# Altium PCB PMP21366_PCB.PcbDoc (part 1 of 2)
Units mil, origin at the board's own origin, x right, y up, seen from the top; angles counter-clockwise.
Board outline 5900 x 4700 mil, 2 copper layers (Top Layer, Bottom Layer), stack 62 mil thick; 89 components, 44 nets, 220 pads, 54 vias.
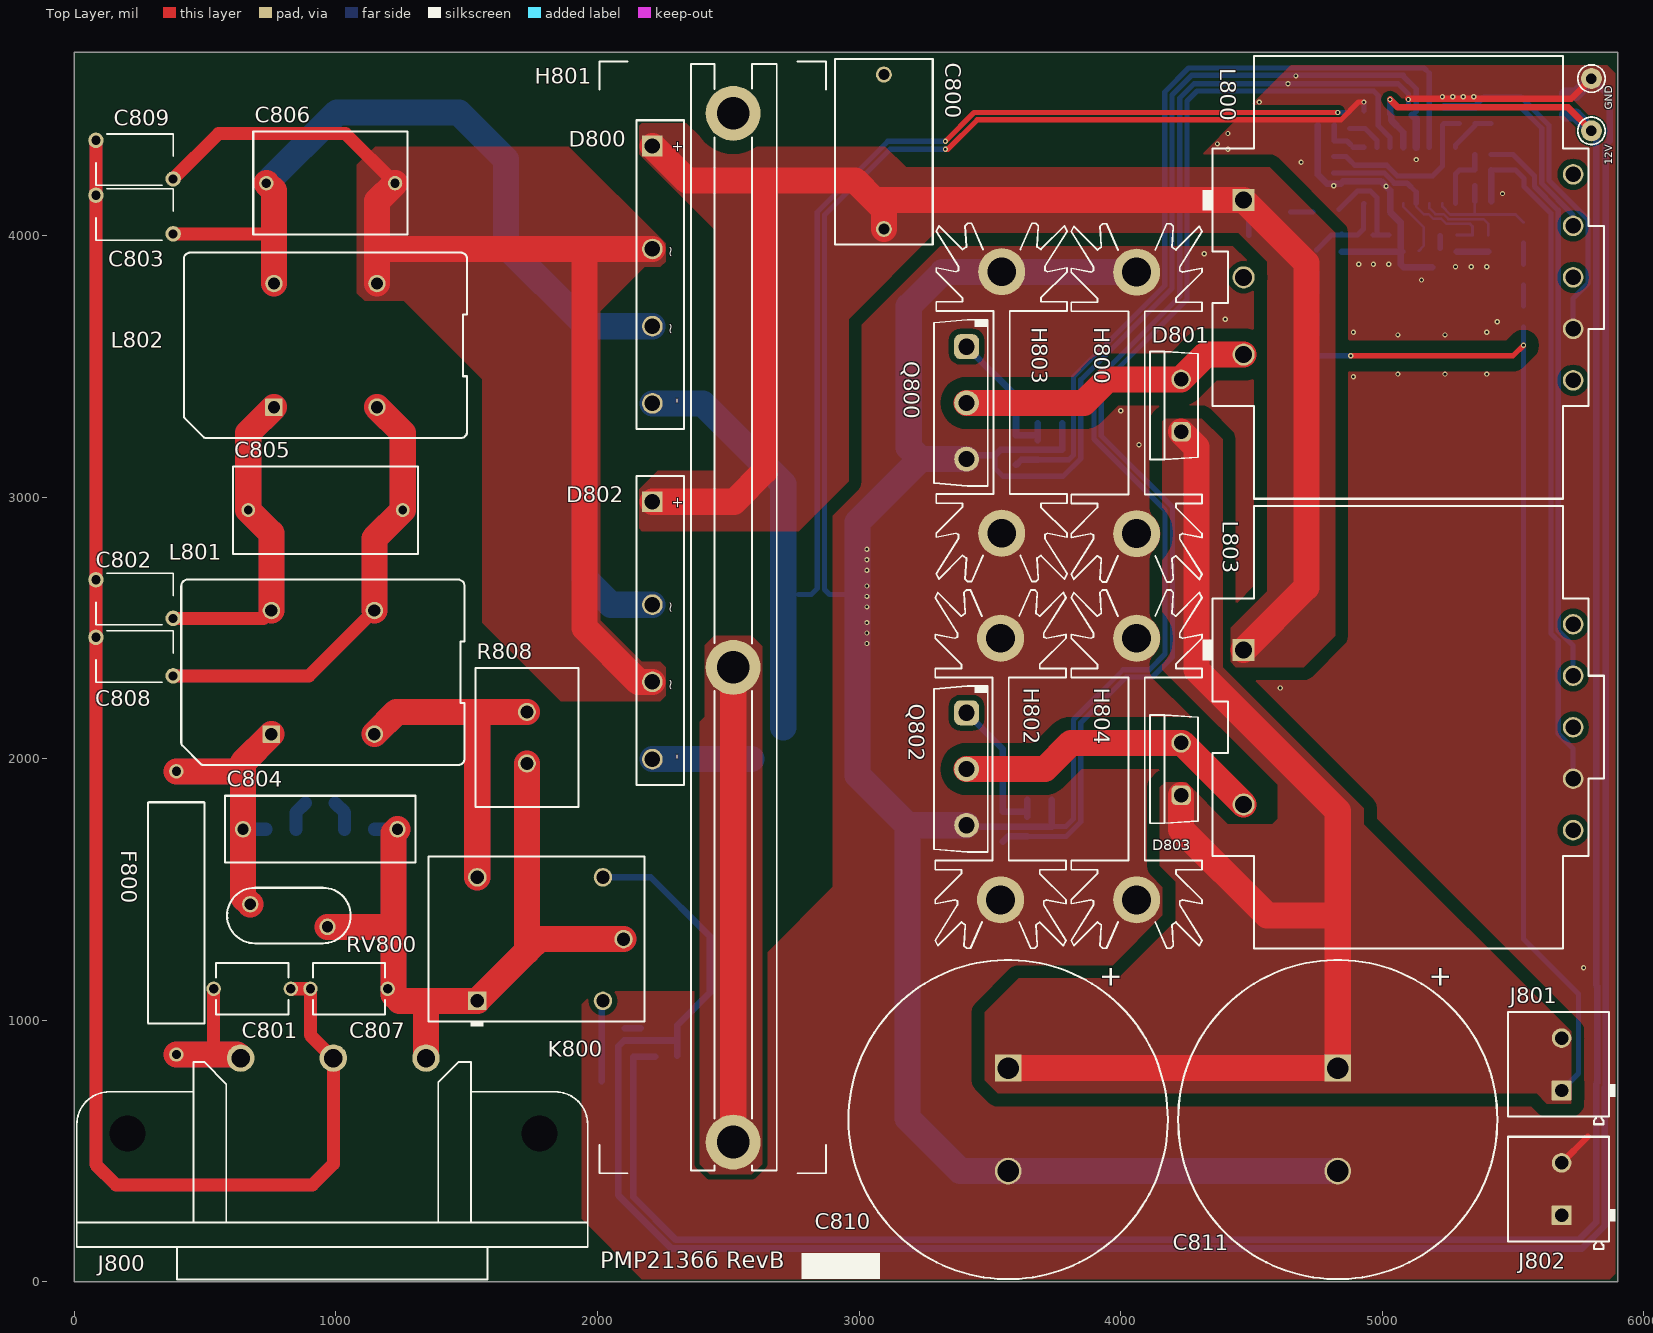
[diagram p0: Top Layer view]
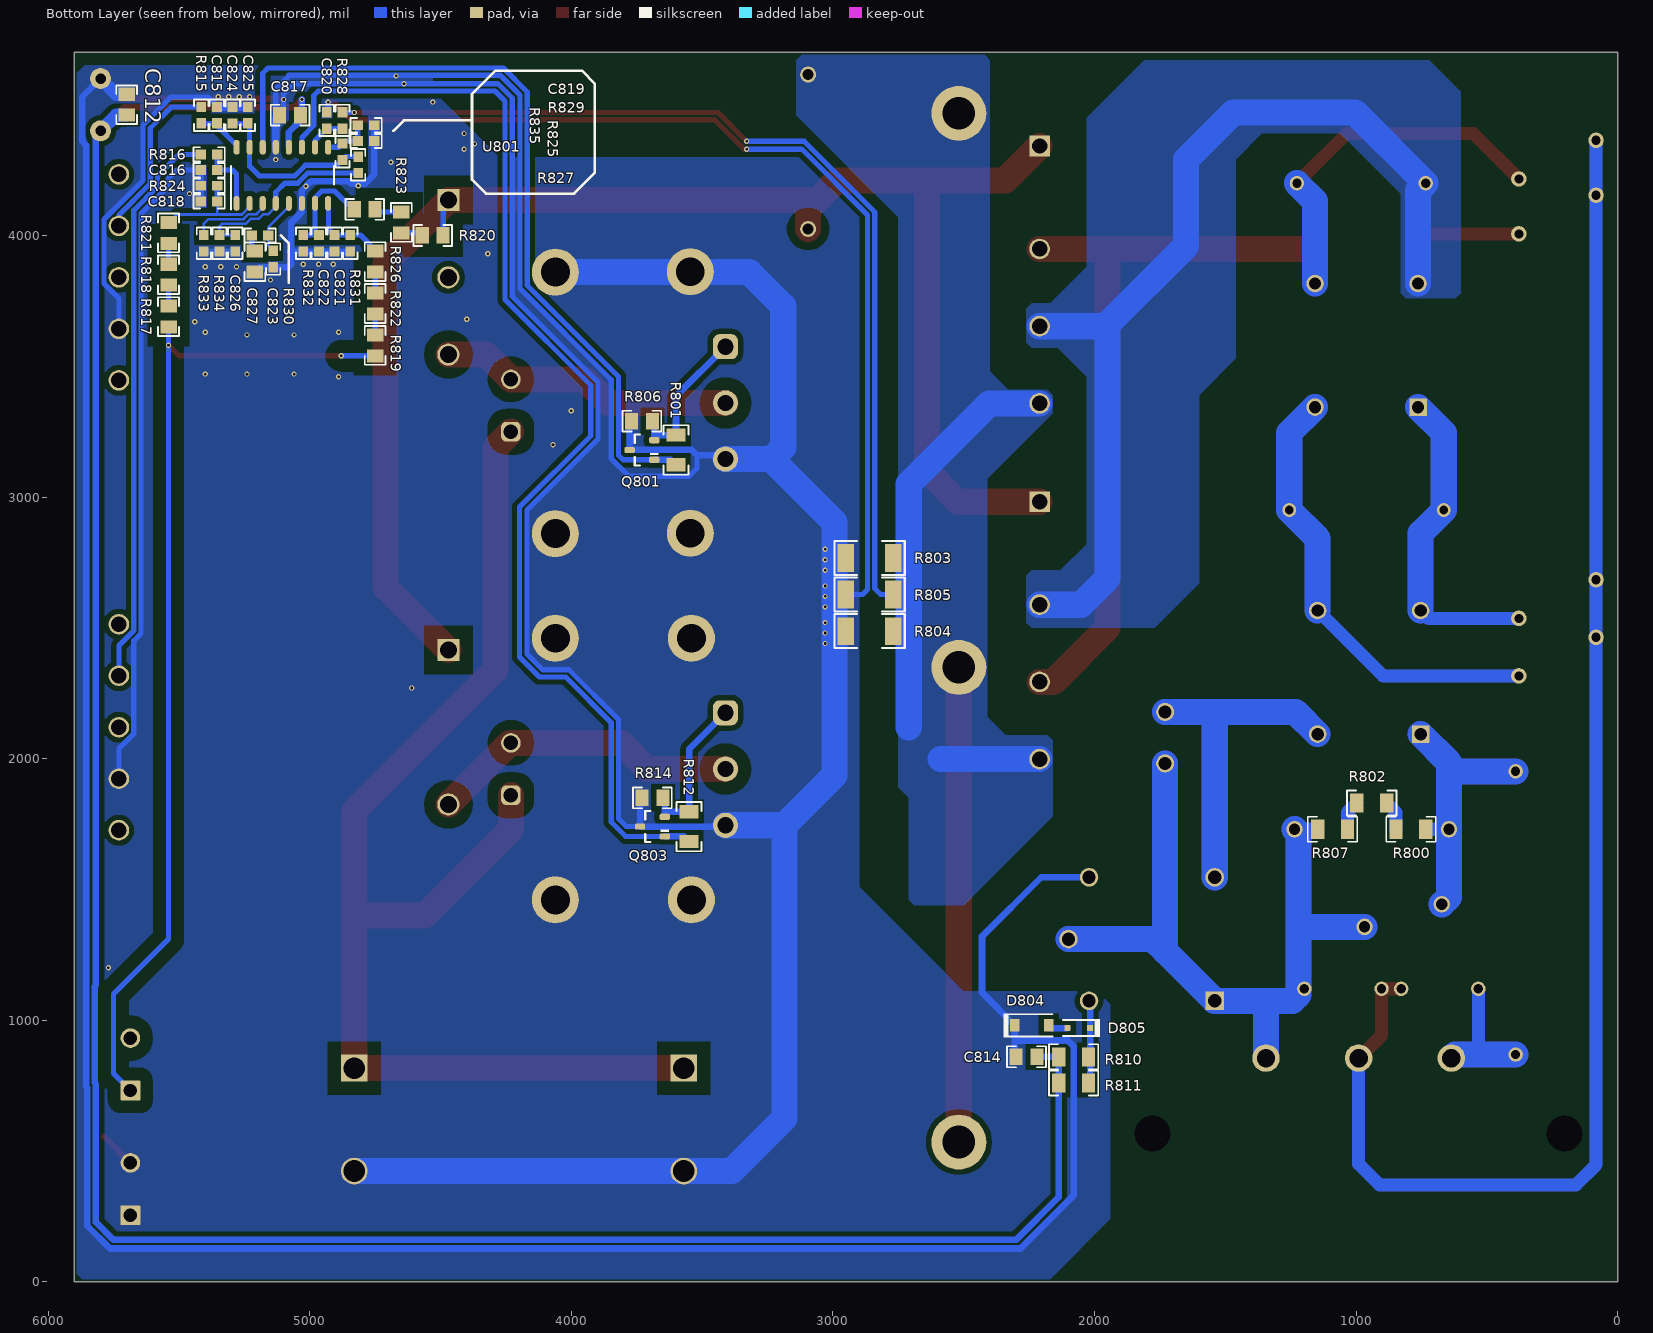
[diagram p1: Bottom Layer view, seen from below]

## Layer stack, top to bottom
Top Solder: solder mask 0.4, Solder Resist, Dk 3.5
Top Layer: signal copper 1.4
Dielectric1: core 59.2, FR-4, Dk 4.8
Bottom Layer: signal copper 1.4
Bottom Solder: solder mask 0.4, Solder Resist, Dk 3.5

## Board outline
0,0 5900,0 5900,4700 0,4700

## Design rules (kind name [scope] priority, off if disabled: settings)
AcuteAngle [All] p1: minimum=4.50000000000000E+0001 checktracksonly=FALSE
AssemblyTestPointUsage [All] p1: valid=2
Clearance Clearance_2 [InNetClass('HV') vs Not InNetClass('HV')] p1: gap=50 ignorepadtopadclearanceinfootprint=FALSE except(0: Arc-Hole Track-Hole SMDPad-Hole THPad-Hole Via-Hole Fill-Hole Poly-Hole Region-Hole Text-Hole)
Clearance Clearance_1 [InNetClass('MV') vs Not InNetClass('MV')] p2: gap=20 ignorepadtopadclearanceinfootprint=FALSE
Clearance Clearance_Keepouts [((IsTrack Or IsArc) And Not InPoly) And IsFree and IsKeepOut vs ((IsTrack Or IsArc) And Not InPoly) And IsFree and IsKeepOut] p3: gap=0 ignorepadtopadclearanceinfootprint=FALSE
Clearance Clearance_BoardEdge_MountingHoles [OnCopper and InComponentClass('Mounting Holes') vs IsKeepOut] p4: gap=40 ignorepadtopadclearanceinfootprint=FALSE except(0: Arc-Hole Track-Hole SMDPad-Hole THPad-Hole Via-Hole Fill-Hole Poly-Hole Region-Hole Text-Hole)
Clearance Clearance_BoardEdge_Poly [OnCopper and InPoly vs IsKeepOut] p5: gap=25 ignorepadtopadclearanceinfootprint=FALSE except(0: Arc-Hole Track-Hole SMDPad-Hole THPad-Hole Via-Hole Fill-Hole Poly-Hole Region-Hole Text-Hole)
Clearance Clearance_BoardEdge [OnCopper and Not InComponentClass('Logo') and not InComponentClass('FiducialMark') and not InRegion(1000,500,4000,800) and Not IsKeepout vs IsKeepOut] p6: gap=75 ignorepadtopadclearanceinfootprint=FALSE except(0: Arc-Hole Track-Hole SMDPad-Hole THPad-Hole Via-Hole Fill-Hole Poly-Hole Region-Hole Text-Hole)
Clearance Clearance_Poly [InPolygon] p7: gap=20 ignorepadtopadclearanceinfootprint=FALSE except(0: Arc-Hole Track-Hole SMDPad-Hole THPad-Hole Via-Hole Fill-Hole Poly-Hole Region-Hole Text-Hole)
Clearance [All] p8: gap=7.87 ignorepadtopadclearanceinfootprint=FALSE except(0: Arc-Hole Track-Hole SMDPad-Hole THPad-Hole Via-Hole Fill-Hole Poly-Hole Region-Hole Text-Hole)
ComponentClearance ComponentClearance_MountingHoles_FiducialMarks [InComponentClass('Mounting Holes') vs InComponentClass('FiducialMark')] p1: gap=20 collisioncheckmode=3 verticalgap=10 showdistances=FALSE
ComponentClearance ComponentClearance_Shunt [InComponentClass('Header') vs InComponentClass('Shunt')] p2: gap=0 collisioncheckmode=3 verticalgap=0 showdistances=FALSE
ComponentClearance ComponentClearance_Logo [InComponentClass('Logo')] p3: gap=5 collisioncheckmode=3 verticalgap=10 showdistances=FALSE
ComponentClearance ComponentClearance_ScrewToNut [(HasFootprint('NY PMS 440 0025 PH')) vs (HasFootprint('Keystone_1902C'))] p4: gap=20 collisioncheckmode=3 verticalgap=100000 showdistances=FALSE
ComponentClearance ComponentClearance_MountingHoles [InComponentClass('Mounting Holes')] p5: gap=20 collisioncheckmode=3 verticalgap=10 showdistances=FALSE
ComponentClearance ComponentClearance_SmallPassives [HasFootprint('0201*') or HasFootprint('0402*') or HasFootprint('0508') or HasFootprint('0603*') or HasFootprint('0612') or HasFootprint('0805*') or HasFootprint('0815*') or HasFootprint('0830*') or HasFootprint('1206*') or HasFootprint('1210*') or HasFootprint('1808*') or HasFootprint('1812*') or HasFootprint('1825*') or HasFootprint('2010*') or HasFootprint('2220*') or HasFootprint('2225*') or HasFootprint('2512*') or HasFootprint('2728*') or HasFootprint('3518*') vs HasFootprint('0201*') or HasFootprint('0402*') or HasFootprint('0508') or HasFootprint('0603*') or HasFootprint('0612') or HasFootprint('0805*') or HasFootprint('0815*') or HasFootprint('0830*') or HasFootprint('1206*') or HasFootprint('1210*') or HasFootprint('1808*') or HasFootprint('1812*') or HasFootprint('1825*') or HasFootprint('2010*') or HasFootprint('2220*') or HasFootprint('2225*') or HasFootprint('2512*') or HasFootprint('2728*') or HasFootprint('3518*')] p6: gap=20 collisioncheckmode=3 verticalgap=20 showdistances=FALSE
ComponentClearance ComponentClearance_THtoSMT [IsThruComponent vs IsSMTComponent] p7: gap=10 collisioncheckmode=3 verticalgap=10 showdistances=FALSE
ComponentClearance ComponentClearance_THtoTH [IsThruComponent vs IsThruComponent] p8: gap=10 collisioncheckmode=3 verticalgap=10 showdistances=FALSE
ComponentClearance [All] p9: gap=10 collisioncheckmode=3 verticalgap=10 showdistances=FALSE
DiffPairsRouting [All] p1: maxlimit=100 minlimit=10 mostfreqgap=10 toplayer_minwidth=15 toplayer_maxwidth=15 toplayer_prefwidth=15 bottomlayer_minwidth=15 bottomlayer_maxwidth=15 bottomlayer_prefwidth=15 maxuncoupledlength=1000
FabricationTestPointUsage TestPointUsage [All] p1: valid=2 allowmultiple=FALSE
FabricationTestpoint Testpoint [All] p1: side=3 testpointundercomponent=TRUE minsize=40 maxsize=100 preferedsize=60 minholesize=0 maxholesize=40 preferedholesize=32 testpointgrid=1 allowsidetop=TRUE allowsidebottom=TRUE usegrid=TRUE gridtolerance=0.01
FanoutControl Fanout_LCC [IsLCC] p1: bgadir=Out bgaviamode=Centered fanoutstyle=Auto fanoutdirection=Alternating viagrid=1 // Fanout_LCC (Default Rule)
FanoutControl Fanout_BGA [IsBGA] p2: bgadir=Out bgaviamode=Centered fanoutstyle=Auto fanoutdirection=Alternating viagrid=1 // Fanout_BGA (Default Rule)
FanoutControl Fanout_Default [All] p4: bgadir=Out bgaviamode=Centered fanoutstyle=Auto fanoutdirection=Alternating viagrid=1 // Fanout_Default (Default Rule)
FanoutControl Fanout_Small [(CompPinCount < 5)] p5: bgadir=Out bgaviamode=Centered fanoutstyle=Auto fanoutdirection=OutThenIn viagrid=1 // Fanout_Small (Default Rule)
Height [All] p1: minheight=0 maxheight=3000 prefheight=500
HoleSize [All] p1: absolutevalues=TRUE maxlimit=251 minlimit=7 maxpercent=80.000 minpercent=20.000
MinimumAnnularRing MinimumAnnularRing_ThermalPadVias [IsVia and InAnyComponent] p1: minimumring=5.91
MinimumAnnularRing [All] p2: minimumring=4.9
MinimumSolderMaskSliver MinimumSolderMaskSliver_Logo [InComponentClass('Logo') vs InComponentClass('Logo')] p1: minsoldermaskwidth=0.7
MinimumSolderMaskSliver [All] p2: minsoldermaskwidth=2
PlaneConnect [All] p1: planeconnectstyle=Direct reliefexpansion=10 reliefentries=4 reliefconductorwidth=10 reliefairgap=10
PolygonConnect PolygonConnect_18 [All vs IsNamedPolygon('C803_2') Or  IsNamedPolygon('VBulk') Or  IsNamedPolygon('C806_2') Or  IsNamedPolygon('GND1') Or  IsNamedPolygon('VBulk') Or  IsNamedPolygon('D801_3') Or  IsNamedPolygon('VAC') Or  IsNamedPolygon('VN') Or  IsNamedPolygon('D803_3') Or  IsNamedPolygon('GND1')] p1: connectstyle=Direct reliefconductorwidth=10 reliefentries=4 polygonreliefangle="90 Angle" airgapwidth=10
PolygonConnect PolygonConnect_17 [All vs IsNamedPolygon('VAC') Or  IsNamedPolygon('VBulk') Or  IsNamedPolygon('D803_3') Or  IsNamedPolygon('VBulk') Or  IsNamedPolygon('D801_3') Or  IsNamedPolygon('C806_2') Or  IsNamedPolygon('C803_2') Or  IsNamedPolygon('VN')] p2: connectstyle=Direct reliefconductorwidth=10 reliefentries=4 polygonreliefangle="90 Angle" airgapwidth=10
PolygonConnect PolygonConnect_16 [All vs IsNamedPolygon('C806_2') Or  IsNamedPolygon('VAC') Or  IsNamedPolygon('C803_2')] p3: connectstyle=Direct reliefconductorwidth=10 reliefentries=4 polygonreliefangle="90 Angle" airgapwidth=10
PolygonConnect PolygonConnect_15 [All vs IsNamedPolygon('C109_2') Or  IsNamedPolygon('C107_2') Or  IsNamedPolygon('HV') Or  IsNamedPolygon('Q203_5') Or  IsNamedPolygon('C107_2') Or  IsNamedPolygon('HS') Or  IsNamedPolygon('Q201_5') Or  IsNamedPolygon('Q203_5') Or  IsNamedPolygon('C106_2') Or  IsNamedPolygon('C108_2') Or  IsNamedPolygon('Vout') Or  IsNamedPolygon('Q203_5') Or  IsNamedPolygon('C108_2') Or  IsNamedPolygon('C113_2') Or  IsNamedPolygon('Q203_5') Or  IsNamedPolygon('Q201_5') Or  IsNamedPolygon('C107_2') Or  IsNamedPolygon('C102_1') Or  IsNamedPolygon('SGND') Or  IsNamedPolygon('GND') Or  IsNamedPolygon('SGND') Or  IsNamedPolygon('GND') Or  IsNamedPolygon('IN+') Or  IsNamedPolygon('IN+') Or  IsNamedPolygon('Q201_5') Or  IsNamedPolygon('Q201_5') Or  IsNamedPolygon('SGND') Or  IsNamedPolygon('SGND') Or  IsNamedPolygon('Vout') Or  IsNamedPolygon('Vout') Or  IsNamedPolygon('IN+') Or  IsNamedPolygon('GND') Or  IsNamedPolygon('IN+') Or  IsNamedPolygon('GND')] p4: connectstyle=Direct reliefconductorwidth=10 reliefentries=4 polygonreliefangle="90 Angle" airgapwidth=10
PolygonConnect PolygonConnect_14 [All vs IsNamedPolygon('C106_2') Or  IsNamedPolygon('C107_2') Or  IsNamedPolygon('C107_2') Or  IsNamedPolygon('C107_2') Or  IsNamedPolygon('C102_1') Or  IsNamedPolygon('Q203_5') Or  IsNamedPolygon('Vout') Or  IsNamedPolygon('Q203_5') Or  IsNamedPolygon('Q203_5') Or  IsNamedPolygon('Q201_5') Or  IsNamedPolygon('C108_2') Or  IsNamedPolygon('Q203_5') Or  IsNamedPolygon('HS') Or  IsNamedPolygon('HV') Or  IsNamedPolygon('C108_2') Or  IsNamedPolygon('Q201_5') Or  IsNamedPolygon('C109_2') Or  IsNamedPolygon('Q201_5') Or  IsNamedPolygon('Q201_5') Or  IsNamedPolygon('C113_2')] p5: connectstyle=Direct reliefconductorwidth=10 reliefentries=4 polygonreliefangle="90 Angle" airgapwidth=10
PolygonConnect PolygonConnect_13 [All vs IsNamedPolygon('C102_1') Or  IsNamedPolygon('HV') Or  IsNamedPolygon('C107_2') Or  IsNamedPolygon('C109_2') Or  IsNamedPolygon('C107_2') Or  IsNamedPolygon('C108_2') Or  IsNamedPolygon('C106_2') Or  IsNamedPolygon('C108_2') Or  IsNamedPolygon('C113_2') Or  IsNamedPolygon('C107_2')] p6: connectstyle=Direct reliefconductorwidth=10 reliefentries=4 polygonreliefangle="90 Angle" airgapwidth=10
PolygonConnect PolygonConnect_12 [All vs IsNamedPolygon('C107_2') Or  IsNamedPolygon('C113_2') Or  IsNamedPolygon('C106_2') Or  IsNamedPolygon('C107_2') Or  IsNamedPolygon('C107_2') Or  IsNamedPolygon('C102_1')] p7: connectstyle=Direct reliefconductorwidth=10 reliefentries=4 polygonreliefangle="90 Angle" airgapwidth=10
PolygonConnect PolygonConnect_11 [All vs IsNamedPolygon('C106_2') Or  IsNamedPolygon('C102_1') Or  IsNamedPolygon('C107_2') Or  IsNamedPolygon('C107_2') Or  IsNamedPolygon('C107_2')] p8: connectstyle=Direct reliefconductorwidth=10 reliefentries=4 polygonreliefangle="90 Angle" airgapwidth=10
PolygonConnect PolygonConnect_10 [All vs IsNamedPolygon('C106_2')] p9: connectstyle=Direct reliefconductorwidth=10 reliefentries=4 polygonreliefangle="90 Angle" airgapwidth=10
PolygonConnect PolygonConnect_9 [All vs IsNamedPolygon('C11_1') Or  IsNamedPolygon('Vin') Or  IsNamedPolygon('Vin') Or  IsNamedPolygon('5V') Or  IsNamedPolygon('D6_2') Or  IsNamedPolygon('Q3_3') Or  IsNamedPolygon('GND2') Or  IsNamedPolygon('GND2') Or  IsNamedPolygon('GND') Or  IsNamedPolygon('Q3_4') Or  IsNamedPolygon('12V5') Or  IsNamedPolygon('GND') Or  IsNamedPolygon('12V5') Or  IsNamedPolygon('D3_1')] p10: connectstyle=Direct reliefconductorwidth=10 reliefentries=4 polygonreliefangle="90 Angle" airgapwidth=10
PolygonConnect PolygonConnect_8 [All vs IsNamedPolygon('C11_1') Or  IsNamedPolygon('Vin') Or  IsNamedPolygon('12V5') Or  IsNamedPolygon('Q3_3') Or  IsNamedPolygon('GND2') Or  IsNamedPolygon('GND2') Or  IsNamedPolygon('5V') Or  IsNamedPolygon('Q3_4') Or  IsNamedPolygon('12V5')] p11: connectstyle=Direct reliefconductorwidth=10 reliefentries=4 polygonreliefangle="90 Angle" airgapwidth=10
PolygonConnect PolygonConnect_7 [All vs IsNamedPolygon('GND2') Or  IsNamedPolygon('GND2') Or  IsNamedPolygon('5V') Or  IsNamedPolygon('12V5') Or  IsNamedPolygon('12V5') Or  IsNamedPolygon('C11_1')] p12: connectstyle=Direct reliefconductorwidth=10 reliefentries=4 polygonreliefangle="90 Angle" airgapwidth=10
PolygonConnect PolygonConnect_6 [All vs IsNamedPolygon('GND2') Or  IsNamedPolygon('SGND') Or  IsNamedPolygon('GND1') Or  IsNamedPolygon('C901_1') Or  IsNamedPolygon('SGND') Or  IsNamedPolygon('GND2') Or  IsNamedPolygon('GND1')] p13: connectstyle=Direct reliefconductorwidth=10 reliefentries=4 polygonreliefangle="90 Angle" airgapwidth=10
PolygonConnect PolygonConnect_5 [All vs IsNamedPolygon('GND1') Or  IsNamedPolygon('GND1')] p14: connectstyle=Direct reliefconductorwidth=10 reliefentries=4 polygonreliefangle="90 Angle" airgapwidth=10
PolygonConnect PolygonConnect_4 [All vs IsNamedPolygon('C21_1') Or  IsNamedPolygon('C5_1') Or  IsNamedPolygon('C12_2') Or  IsNamedPolygon('C2_2') Or  IsNamedPolygon('C13_1') Or  IsNamedPolygon('C28_1') Or  IsNamedPolygon('C6_1') Or  IsNamedPolygon('GND') Or  IsNamedPolygon('GND2') Or  IsNamedPolygon('C14_1') Or  IsNamedPolygon('C13_1') Or  IsNamedPolygon('Q1_3') Or  IsNamedPolygon('C14_1') Or  IsNamedPolygon('C5_1') Or  IsNamedPolygon('GND2') Or  IsNamedPolygon('C28_1') Or  IsNamedPolygon('D5_2') Or  IsNamedPolygon('D6_2') Or  IsNamedPolygon('D2_1') Or  IsNamedPolygon('C12_2') Or  IsNamedPolygon('D2_1') Or  IsNamedPolygon('C4_1') Or  IsNamedPolygon('C4_1') Or  IsNamedPolygon('C2_2') Or  IsNamedPolygon('GND') Or  IsNamedPolygon('C33_1') Or  IsNamedPolygon('C9_1')] p15: connectstyle=Direct reliefconductorwidth=10 reliefentries=4 polygonreliefangle="90 Angle" airgapwidth=10
PolygonConnect PolygonConnect_3 [All vs IsNamedPolygon('C28_1') Or  IsNamedPolygon('C12_2') Or  IsNamedPolygon('C28_1') Or  IsNamedPolygon('C9_1') Or  IsNamedPolygon('D5_2') Or  IsNamedPolygon('C12_2') Or  IsNamedPolygon('C2_2') Or  IsNamedPolygon('C14_1') Or  IsNamedPolygon('C4_1') Or  IsNamedPolygon('C14_1') Or  IsNamedPolygon('D6_2') Or  IsNamedPolygon('GND2') Or  IsNamedPolygon('Q1_3') Or  IsNamedPolygon('C5_1') Or  IsNamedPolygon('D2_1') Or  IsNamedPolygon('C4_1') Or  IsNamedPolygon('C13_1') Or  IsNamedPolygon('C5_1') Or  IsNamedPolygon('C13_1') Or  IsNamedPolygon('C33_1') Or  IsNamedPolygon('D2_1') Or  IsNamedPolygon('GND') Or  IsNamedPolygon('GND') Or  IsNamedPolygon('GND2') Or  IsNamedPolygon('C2_2') Or  IsNamedPolygon('C6_1') Or  IsNamedPolygon('C21_1')] p16: connectstyle=Direct reliefconductorwidth=10 reliefentries=4 polygonreliefangle="90 Angle" airgapwidth=10
PolygonConnect PolygonConnect_2 [All vs IsNamedPolygon('C21_1') Or  IsNamedPolygon('C4_1') Or  IsNamedPolygon('D5_2') Or  IsNamedPolygon('C5_1') Or  IsNamedPolygon('C14_1') Or  IsNamedPolygon('C13_1') Or  IsNamedPolygon('C4_1') Or  IsNamedPolygon('C33_1') Or  IsNamedPolygon('C12_2') Or  IsNamedPolygon('D2_1') Or  IsNamedPolygon('C2_2') Or  IsNamedPolygon('C28_1') Or  IsNamedPolygon('C12_2') Or  IsNamedPolygon('D2_1') Or  IsNamedPolygon('C5_1') Or  IsNamedPolygon('Q1_3') Or  IsNamedPolygon('GND') Or  IsNamedPolygon('D6_2') Or  IsNamedPolygon('C6_1') Or  IsNamedPolygon('C2_2') Or  IsNamedPolygon('C14_1') Or  IsNamedPolygon('C28_1') Or  IsNamedPolygon('C13_1') Or  IsNamedPolygon('C9_1') Or  IsNamedPolygon('GND')] p17: connectstyle=Direct reliefconductorwidth=10 reliefentries=4 polygonreliefangle="90 Angle" airgapwidth=10
PolygonConnect PolygonConnect_1 [All vs IsNamedPolygon('C28_1') Or  IsNamedPolygon('D5_2') Or  IsNamedPolygon('C5_1') Or  IsNamedPolygon('C5_1') Or  IsNamedPolygon('D2_1') Or  IsNamedPolygon('C21_1') Or  IsNamedPolygon('C9_1') Or  IsNamedPolygon('C4_1') Or  IsNamedPolygon('C14_1') Or  IsNamedPolygon('C28_1') Or  IsNamedPolygon('C6_1') Or  IsNamedPolygon('C12_2') Or  IsNamedPolygon('C33_1') Or  IsNamedPolygon('C4_1') Or  IsNamedPolygon('C13_1') Or  IsNamedPolygon('C12_2') Or  IsNamedPolygon('D6_2') Or  IsNamedPolygon('C2_2') Or  IsNamedPolygon('C14_1') Or  IsNamedPolygon('D2_1') Or  IsNamedPolygon('C2_2') Or  IsNamedPolygon('C13_1')] p18: connectstyle=Direct reliefconductorwidth=10 reliefentries=4 polygonreliefangle="90 Angle" airgapwidth=10
PolygonConnect [All] p19: connectstyle=Relief reliefconductorwidth=10 reliefentries=4 polygonreliefangle="90 Angle" airgapwidth=10
RoutingVias ThermalPadVias [IsVia and InAnyComponent] p1: holewidth=7.87 width=19.68 viastyle="Through Hole" minholewidth=7.87 minwidth=19.68 maxholewidth=12.99 maxwidth=23.62
RoutingVias [All] p2: holewidth=16 width=34 viastyle="Through Hole" minholewidth=7.87 minwidth=20 maxholewidth=40 maxwidth=65
SilkToBoardRegionClearance [Not ((IsComment or IsDesignator) And (Hide <> 'False')) and not InRegion(1000,500,4000,800)] p1:
SilkToSilkClearance SilkToSilkClearance_Pb-FreeLogo [(HasFootprint('Pb-Free_Overlay_Medium') OR HasFootprint('Pb-Free_Overlay_Small')) vs (HasFootprint('Pb-Free_Overlay_Medium') OR HasFootprint('Pb-Free_Overlay_Small'))] p1: silktosilkclearance=0
SilkToSilkClearance [All] p2: silktosilkclearance=1
SilkToSolderMaskClearance "Silk to Solder Mask Opening" [All] p1: minsilkscreentomaskgap=1 clearancetoexposedcopper=FALSE
SolderMaskExpansion [All] p1: expansion=1.97
Width [All] p1: maxlimit=100 minlimit=6 preferedwidth=10 checkconnectedcopper=TRUE
14 further rules are at their usual default settings.

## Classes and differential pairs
net class HV: NetC801_2 NetC802_2 NetC803_2 NetC804_1 NetC804_2 NetC805_2 NetC806_2 NetD801_3 NetD803_3 NetK800_2 NetR800_1 NetR802_1 NetR817_1 NetR818_1 NetR819_1 NetR820_1 NetR822_1 NetR823_1 VAC VBulk

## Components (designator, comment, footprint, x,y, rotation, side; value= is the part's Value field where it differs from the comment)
12V "5000" Keystone5000 5800,4400 r90 top (schematic designator TP800)
C800 "450MPK105J" MPK_1800x950 3094.72,4320 r90 top value=1uF
C801 "DE2B3KY101KN3AU02F" KY_700x500x1000 680,1120 r180 top value=100pF
C802 "DE2B3KY221KA3BU02F" VY2_750x500 230,2610 r0 top value=220pF
C803 "DE2B3KY221KA3BU02F" VY2_750x500 230,4080 r0 top value=220pF
C804 "890324025017" WCAP-FTX2_1800x600x1200 940,1730 r0 top value=0.1uF
C805 "ECQ-U2A224ML" CAPRR1500W60L1750T800H1650 960,2950 r0 top value=0.22uF
C806 "890324024005" WCAP-FTX2_1500x1000x1600 980,4200 r0 top value=0.47uF
C807 "DE2B3KY101KN3AU02F" KY_700x500x1000 1050,1120 r180 top value=100pF
C808 "DE2B3KY221KA3BU02F" VY2_750x500 230,2390 r180 top value=220pF
C809 "DE2B3KY221KA3BU02F" VY2_750x500 230,4290 r180 top value=220pF
C810 "450VXH270MEFCSN30X30" 380LQ_3000x3000 3570,620 r270 top value=270uF
C811 "450VXH270MEFCSN30X30" 380LQ_3000x3000 4830,620 r270 top value=270uF
C812 "0805YD225KAT2A" 0805_HV 5700,4500 r90 bottom value=2.2uF
C814 "0805YD105KAT2A" 0805_HV 2260,860 r180 bottom value=1uF
C815 "C0603C220J5GACTU" 0603 5355,4460 r90 bottom value=22pF
C816 "C0603C220J5GACTU" 0603 5385,4250 r0 bottom value=22pF
C817 "0805YD225KAT2A" 0805_HV 5075,4460 r0 bottom value=2.2uF
C818 "06031C122JAT2A" 0603 5385,4130 r0 bottom value=1200pF
C819 "06031C122JAT2A" 0603 4785,4421.3 r180 bottom value=1200pF
C820 "06031C122JAT2A" 0603 4935,4440 r90 bottom value=1200pF
C821 "GRM188R71H681KA01D" 0603 4905,3970 r270 bottom value=680pF
C822 "06031C102MAT2A" 0603 4965,3970 r270 bottom value=1000pF
C823 "GRM188R71H681KA01D" 0603 5140,3910 r270 bottom value=680pF
C824 "UMK107AB7105KA-T" 0603 5295,4459.47 r90 bottom value=1uF
C825 "EMK107B7104KA-T" 0603 5236.93,4460 r90 bottom value=0.1uF
C826 "06031C122JAT2A" 0603 5285,3970 r270 bottom value=1200pF
C827 "0805YD225KAT2A" 0805_HV 5210,3900 r270 bottom value=2.2uF
D800 "D25XB60-7000" 5S 2210,3850 r270 top value=600V
D801 "MUR860G" TO-220AC 4231,3350 r90 top value=0.98V
D802 "D25XB60-7000" 5S 2210,2490 r270 top value=600V
D803 "MUR860G" TO-220AC 4231,1960 r90 top value=0.98V
D804 "MMSZ4699T1G" SOD-123 2240,980 r180 bottom value=12V
D805 "BAS316,115" sod-323 2060,970 r0 bottom value=100V
F800 "0217015.MXEP" Fuse_217_015 390,1410 r270 top
GND "5001" Keystone5001 5800,4600 r90 top (schematic designator TP801)
H800 "513002B02500G" HSINK_513201B02500 4061,3360 r90 top
H801 "782653B04250G" HEATSINK_782653B04250G 2440,2540 r90 top
H802 "513002B02500G" HSINK_513201B02500 3541,1960 r90 top
H803 "513002B02500G" HSINK_513201B02500 3545.25,3361.5 r90 top
H804 "513002B02500G" HSINK_513201B02500 4061,1960 r90 top
J800 "703W-00/54" CONN_QUALTEK-703W-0054 990,460 r180 top
J801 "1715721" PhoenixContact_1715721 5685.67,831.31 r90 top value=2x1
J802 "1715721" PhoenixContact_1715721 5685.67,354.26 r90 top value=2x1
K800 "875B-1CC-F-S-12VDC" RELAY_875 1820,1310 r90 top
L800 "PFC4124QM-161K06D-00" TDK_PFC4124QM-161K06D-00#1 5100,3840 r0 top value="160 uH"
L801 "7448040707" WE-CMBNC_L 950,2330 r90 top value=7mH
L802 "7448040707" WE-CMBNC_L 960,3580 r90 top value=7mH
L803 "PFC4124QM-161K06D-00" TDK_PFC4124QM-161K06D-00#2 5100,2120 r0 top value="160 uH"
Q800 "IPW65R065C7" TO-247 3411,3360 r270 top value=650V
Q801 "FMMT718TA" SOT-23 3730,3180 r0 bottom value=20V
Q802 "IPW65R065C7" TO-247 3411,1960 r270 top value=650V
Q803 "FMMT718TA" SOT-23 3690,1740 r0 bottom value=20V
R800 "CRCW1206432KFKEA" 1206 790,1730 r180 bottom value=432k
R801 "RC1206FR-073RL" 1206 3600,3180 r90 bottom value=3.00
R802 "CRCW1206432KFKEA" 1206 940,1830 r180 bottom value=432k
R803 "CSRN2010FK20L0" 2010 2860,2767.09 r0 bottom value=0.02
R804 "CSRN2010FK20L0" 2010 2860,2487.09 r0 bottom value=0.02
R805 "CSRN2010FK20L0" 2010 2860,2627.09 r0 bottom value=0.02
R806 "CRCW080510K0FKEA" 0805_HV 3730,3290 r180 bottom value=10.0k
R807 "CRCW1206432KFKEA" 1206 1090,1730 r180 bottom value=432k
R808 "TWW10J10RE" TWW10 1730,2080 r270 top value=10
R810 "CRCW120675R0JNEA" 1206 2080,860 r0 bottom value=75
R811 "CRCW120675R0JNEA" 1206 2080,760 r0 bottom value=75
R812 "RC1206FR-073RL" 1206 3550,1740 r90 bottom value=3.00
R814 "CRCW080510K0FKEA" 0805_HV 3690,1850 r180 bottom value=10.0k
R815 "CRCW060320K5FKEA" 0603 5415,4460 r270 bottom value=20.5k
R816 "CRCW060320K5FKEA" 0603 5385,4310 r0 bottom value=20.5k
R817 "CRCW08053M01FKEA" 0805_HV 5540,3690 r270 bottom value=3.01Meg
R818 "CRCW08052M74FKEA" 0805_HV 5540,3850 r270 bottom value=2.74Meg
R819 "CRCW08052M74FKEA" 0805_HV 4750,3580 r270 bottom value=2.74Meg
R820 "CRCW08052M87FKEA" 0805_HV 4530,4000 r180 bottom value=2.87Meg
R821 "CRCW08052M74FKEA" 0805_HV 5540,4010 r270 bottom value=2.74Meg
R822 "CRCW08052M74FKEA" 0805_HV 4750,3740 r270 bottom value=2.74Meg
R823 "CRCW08052M87FKEA" 0805_HV 4650,4050 r270 bottom value=2.87Meg
R824 "CRCW0603133KFKEA" 0603 5385,4190 r180 bottom value=133k
R825 "CRCW0603133KFKEA" 0603 4815,4270 r270 bottom value=133k
R826 "CRCW08052M74FKEA" 0805_HV 4750,3900 r270 bottom value=2.74Meg
R827 "CRCW08052M87FKEA" 0805_HV 4790,4100 r180 bottom value=2.87Meg
R828 "CRCW0603100RFKEA" 0603 4875,4440 r270 bottom value=100
R829 "CRCW060315K0FKEA" 0603 4785,4361.3 r0 bottom value=15.0k
R830 "CRCW060311K3FKEA" 0603 5190,4000 r180 bottom value=11.3k
R831 "CRCW060382K5FKEA" 0603 4845,3970 r90 bottom value=82.5k
R832 "CRCW0603133KFKEA" 0603 5025,3970 r90 bottom value=133k
R833 "CRCW0603121KFKEA" 0603 5405,3970 r90 bottom value=121k
R834 "RC0603FR-0747K5L" 0603 5345,3970 r90 bottom value=47.5k
R835 "CRCW0603133KFKEA" 0603 4875,4320 r90 bottom value=133k
RV800 "S10K275E2" VAR_S10K275E2 820,1400 r180 top
U801 "UCC28064DR" D0016A_N 5105,4230 r90 bottom

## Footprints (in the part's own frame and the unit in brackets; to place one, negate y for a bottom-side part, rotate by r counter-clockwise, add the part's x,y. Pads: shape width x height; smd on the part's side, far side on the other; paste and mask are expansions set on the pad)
5S [mm] "TH, 4-Leads, Body 4.6x30mm"
  rect 2x2 hole 1.5: 1(-12.5,0)
  round 2 hole 1.5: 2(-2.5,0) 3(5,0) 4(12.5,0)
  silkscreen extent -15,-1.55 15,3.05, body extent -15,-1.55 15,3.05, height 24
380LQ_3000x3000 [mm] "TH, 2-Leads, Dia 30mm, Pin Spacing 10mm"
  rect 2.6x2.6 hole 2.1: 1(-5,0)
  round 2.6 hole 2.1: 2(5,0)
  silkscreen extent -15.5,-15.5 15.5,15.5, body extent -15.5,-15.5 15.5,15.5, height 32
0603 [mm] "0603 from SM-752 data"
  rect 1x0.95 smd: 1(-0.8,0) 2(0.8,0)
  silkscreen extent -1.52,-0.69 1.52,0.69, body extent -0.87,-0.47 0.87,0.47, height 1
0805_HV [mil] "0805 with 30mil clearance between pads"
  rect 50x63 smd: 1(-40,0) 2(40,0)
  silkscreen extent -74,-40 74,40, body extent -43,-29 43,29, height 57
1206 [mm] "1206 from SM-752 data"
  rect 1.3x1.85 smd: 1(-1.45,0) 2(1.45,0)
  silkscreen extent -2.4,-1.21 2.4,1.21, body extent -1.7,-0.9 1.7,0.9, height 1.35
2010 [mm] "Chip Capacitor, Body 5.08x2.54mm, IPC Medium Density"
  rect 1.6x2.7 smd: 1(-2.3,0) 2(2.3,0)
  silkscreen extent -3.42,-1.65 3.42,1.65, body extent -2.73,-1.45 2.73,1.45, height 1.66
CAPRR1500W60L1750T800H1650 [mm] "PANASONIC"
  round 1.35 hole 0.85: 1(-7.5,0) 2(7.5,0)
  silkscreen extent -9,-4.25 9,4.25, body extent -9.05,-4.3 9.05,4.3, height 17
CONN_QUALTEK-703W-0054 [mil] "AC Receptacle"
  round 105 hole 70: 1(354.33,-395) 2(-354.33,-395) 3(0,-395)
  round 39.37 hole 137.8 unplated: MH1(-787.4,-107.36) MH2(787.4,-107.36)
  silkscreen extent -972,-380 981,452, body extent -972,-477 981,452, height 1130
D0016A_N [mm] "SOIC, 16-Leads, Body 9.9x3.9mm, Pitch 1.27mm, IPC Medium Density"
  oval 1.45x0.6 smd: 1(-2.725,4.445) 2(-2.725,3.175) 3(-2.725,1.905) 4(-2.725,0.635) 5(-2.725,-0.635) 6(-2.725,-1.905) 7(-2.725,-3.175) 8(-2.725,-4.445) 9(2.725,-4.445) 10(2.725,-3.175) 11(2.725,-1.905) 12(2.725,-0.635) 13(2.725,0.635) 14(2.725,1.905) 15(2.725,3.175) 16(2.725,4.445)
  silkscreen extent -3.3,-5 0.9,5, body extent -3,-4.95 3,4.95, height 1.6
Fuse_217_015 [mm] "TH, 2-Leads, Body 21.5x5.5mm, Pin Spacing 27.5mm"
  round 1.4 hole 0.9: 1(-13.75,0) 2(13.75,0)
  silkscreen extent -10.75,-2.75 10.75,2.75, body extent -14.07,-2.75 14.08,2.75, height 5.5
HEATSINK_782653B04250G [mil] "Aavid"
  round 210 hole 125: 1(-2006.1,-78.66) 2(-191.14,-78.66) 3(1926.97,-78.66)
  silkscreen extent -2125,-433 2125,433, body extent -2125,-430 2120,420, height 1122
HSINK_513201B02500 [mil] "Aavid"
  round 180 hole 110.24: 1(-500,0) 2(500,0)
  silkscreen extent -685,-250 685,250, body extent -685,-250 685,250, height 2000
Keystone5000 [mil] "For Keystone 500x miniature loop terminals"
  round 80 hole 40: 1(0,0)
  silkscreen extent -52,-52 52,52, body extent -49,-49 49,49, height 182
Keystone5001 [mil] "For Keystone 500x miniature loop terminals"
  round 80 hole 40: 1(0,0)
  silkscreen extent -52,-52 52,52, body extent -49,-49 49,49, height 182
KY_700x500x1000 [mm] "TH, 2- Leads, Body 7x5mm, Pin Spacing 7.5mm"
  round 1.4 hole 0.9: 1(-3.75,0) 2(3.75,0)
  silkscreen extent -3.5,-2.5 3.5,2.5, body extent -4.05,-2.5 4.05,2.5, height 9.97
MPK_1800x950 [mm] "TH, 2-Leads, Body 18x9.5mm, Lead Spacing 15mm"
  round 1.55 hole 1.05: 1(-7.5,0) 2(7.5,0)
  silkscreen extent -9,-4.75 9,4.75, body extent -9,-4.75 9,4.75, height 14
PhoenixContact_1715721 [mm] "Phoenix Contact 1715721 used on LM3445 design from Longmont"
  rrect5% 1.905x1.905 hole 1.3: 1(-2.54,0)
  round 1.9 hole 1.3: 2(2.54,0)
  silkscreen extent -5.82,-5.25 5.08,5.2, body extent -5.82,-4.6 5.08,5.2, height 14.2
RELAY_875 [mm] "TH, 5-Leads, Body 21x16mm"
  rect 1.8x1.8 hole 1.3: 1(-6,7.1)
  round 1.8 hole 1.3: 2(6,7.1) 3(0,-7.1) 4(-6,-5.1) 5(6,-5.1)
  silkscreen extent -8.5,-9.15 8,11.85, body extent -8,-9.15 8,11.85, height 20.6
SOD-123 [mm] "On Semi recommended land pattern"
  rect 0.915x1.22 smd: 1(-1.637,0) 2(1.637,0)
  silkscreen extent -2.74,-1.17 2.03,1.17, body extent -1.93,-0.9 1.93,0.9, height 1.35
sod-323 [mm] "NXP recommended land pattern"
  rect 0.6x0.6 smd paste-0.05: 1(-1.1,0) 2(1.1,0)
  silkscreen extent -2.06,-0.86 1.53,0.86, body extent -1.3,-0.67 1.3,0.68, height 1.1
SOT-23 [mm] "SOT23, 3-Leads, Body 2.9x1.3mm, Pitch 0.95mm, Lead Span 2.5mm, IPC Medium Density"
  rrect50% 1x0.6 smd: 1(-1.2,0.95) 2(-1.2,-0.95) 3(1.2,0)
  silkscreen extent -1.62,-1.5 0.7,1.5, body extent -1.16,-1.45 1.21,1.45, height 1
TDK_PFC4124QM-161K06D-00#1 [mm] "TH, 8-Leads, Body 43x38mm"
  rect 2.15x2.15 hole 1.65: 1(-16,7.5)
  round 2.15 hole 1.65: 2(-16,0) 3(-16,-7.5)
  round 2 hole 1.5: 4(16,-10) 5(16,-5) 6(16,0) 7(16,5) 8(16,10)
  silkscreen extent -20,-21.5 19,21.5, body extent -19,-21.5 19,21.5, height 25
TDK_PFC4124QM-161K06D-00#2 [mm] "TH, 8-Leads, Body 43x38mm"
  rect 2.15x2.15 hole 1.65: 1(-16,7.5)
  round 2.15 hole 1.65: 3(-16,-7.5)
  round 2 hole 1.5: 4(16,-10) 5(16,-5) 6(16,0) 7(16,5) 8(16,10)
  silkscreen extent -20,-21.5 19,21.5, body extent -19,-21.5 19,21.5, height 25
TO-220AC [mm]
  rrect50% 1.9x1.9 hole 1.4: 1(-2.54,0)
  round 1.9 hole 1.4: 3(2.54,0)
  silkscreen extent -5.25,-1.64 5.26,3.01, body extent -5.25,-1.64 5.26,3.01, height 19.09
TO-247 [mil] "Standard TO-247"
  rrect50% 95x95 hole 62: 1(-215,0)
  round 95 / inner round 74.8 / far side round 96 hole 62: 2(0,0) 3(215,0)
  silkscreen extent -318,-124 318,81, body extent -318,-124 318,81, height 1007
TWW10 [mm] "TH, 2-Leads, Body 13.5x10mm, Pin Spacing 5mm"
  round 1.75 hole 1.25: 1(-2.5,0) 2(2.5,0)
  silkscreen extent -6.75,-5 6.75,5, body extent -6.7,-5 6.81,5, height 50
VAR_S10K275E2 [mm] "EPCOS"
  round 1.6 hole 1.1: 1(-3.75,1.1) 2(3.75,-1.1)
  silkscreen extent -6,-2.7 6,2.7, body extent -5.98,-2.7 5.98,2.7, height 14.99
VY2_750x500 [mm] "Vishay"
  round 1.5 hole 0.889: 1(-3.75,1.875) 2(3.75,-1.875)
  silkscreen extent -3.75,-2.5 3.75,2.5, body extent -4.05,-2.5 4.05,2.5, height 10.49
WCAP-FTX2_1500x1000x1600 [mm] "TH, 2-Leads, Body 15x10mm, Pin Spacing 12.5mm"
  round 1.4 hole 0.9: 1(-6.25,0) 2(6.25,0)
  silkscreen extent -7.52,-5 7.48,5, body extent -7.5,-5 7.5,5, height 16
WCAP-FTX2_1800x600x1200 [mm] "TH, 2-Leads, Body 18x6mm, Lead Spacing 15mm"
  round 1.6 hole 1.1: 1(-7.5,0) 2(7.5,0)
  silkscreen extent -9.25,-3.25 9.25,3.25, body extent -9.25,-3.25 9.25,3.25, height 12.5
WE-CMBNC_L [mm] "TH, 4-Leads, Body 19x28mm"
  rrect6% 1.7x1.7 hole 1.2: 1(-6,5)
  round 1.7 hole 1.2: 2(-6,-5) 3(6,-5) 4(6,5)
  silkscreen extent -9,-13.75 9,13.75, body extent -9,-13.75 9,13.75, height 25.47

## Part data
12V: "Test Point, Miniature, Red, TH", Color=Red, Manufacturer=Keystone, Supplier Part Number 1=36-5000-ND
C800: "CAP, Film, 1 µF, 450 V,+/- 5%, TH", Cap_Case=18x9.5mm, Manufacturer=Rubycon, Supplier Part Number 1=1189-1822-ND, Tolerance_%=5, Value2=450V, ValueDisplayed=1µF
C801 C807: "CAP, CERM, 100 pF, X1 250 VAC/Y2 300 VAC, +/- 10%, B, TH, 2- Leads, Body 7x5mm, Pin Spacing 7.5mm", Cap_Case=7x5x10mm, Manufacturer=MuRata, Supplier Part Number 1=490-9533-1-ND, TempCo=B, Tolerance_%=10, ValueDisplayed=100pF
C802 C803 C808 C809: library part VY2471K29Y5SS63V7, "CAP CER 220PF 300VAC 10% RADIAL", Cap_Case="Disk, 5x7.5 mm", Manufacturer=Murata, Supplier Part Number 1=490-9434-ND, TempCo=VY2, Tolerance_%=10, Value1=Unknown, Value2=300V, ValueDisplayed=220pF
C804: "CAP, Film, 0.1 µF, X2 275 VAC, +/- 10%, TH", Cap_Case=18x6x12mm, Manufacturer="Wurth Elektronik", Supplier Part Number 1=732-5898-ND, Tolerance_%=10, ValueDisplayed=0.1µF
C805: "CAP, Film, 0.22 µF, 275 V,+/- 20%, TH", Cap_Case="Radial 17.5x8x16.5", Manufacturer=Panasonic, Supplier Part Number 1=P10732-ND, Tolerance_%=20, Value2=275V, ValueDisplayed=0.22µF
C806: "CAP, Film, 0.47 µF, X2 275 VAC, +/- 10%, TH", Cap_Case=15x10x16mm, Manufacturer="Wurth Elektronik", Supplier Part Number 1=732-5890-ND, Tolerance_%=10, ValueDisplayed=0.47µF
C810 C811: library part 380LQ271M450K022, "CAP ALUM 270UF 450V 20% SNAP", Cap_Case=30x30mm, Manufacturer=Rubycon, Supplier Part Number 1=1189-2036-ND, Tolerance_%=20, Value1="0.737 ohm", Value2=450V, ValueDisplayed=270µF
C812 C817 C827: "CAP, CERM, 2.2 µF, 16 V, +/- 10%, X5R, 0805", Cap_Case=0805, Manufacturer=AVX, Supplier Part Number 1=478-2580-1-ND, TempCo=X5R, Tolerance_%=10, Value1="0.009 ohm", Value2=16V, ValueDisplayed=2.2µF
C814: "CAP, CERM, 1uF, 16V, +/-10%, X5R, 0805", Cap_Case=0805, Manufacturer=AVX, Supplier Part Number 1=478-1411-1-ND, TempCo=X5R, Tolerance_%=10, Value1="0.012 ohm", Value2=16V, ValueDisplayed=1µF
C815 C816: "CAP, CERM, 22 pF, 50 V, +/- 5%, C0G/NP0, 0603", Cap_Case=0603, Manufacturer=Kemet, Supplier Part Number 1=399-1053-1-ND, TempCo=C0G/NP0, Tolerance_%=5, Value1=Unknown, Value2=50V, ValueDisplayed=22pF
C818 C819 C820 C826: "CAP, CERM, 1200 pF, 100 V,+/- 5%, X7R, 0603", Cap_Case=0603, Manufacturer=AVX, Supplier Part Number 1=478-3702-1-ND, TempCo=X7R, Tolerance_%=5, Value1="0.254 ohm", Value2=100V, ValueDisplayed=1200pF
C821 C823: "CAP, CERM, 680 pF, 50 V, +/- 10%, X7R, 0603", Cap_Case=0603, Manufacturer=MuRata, Supplier Part Number 1=490-1491-1-ND, TempCo=X7R, Tolerance_%=10, Value1=Unknown, Value2=50V, ValueDisplayed=680pF
C822: "CAP, CERM, 1000 pF, 100 V, +/- 20%, X7R, 0603", Cap_Case=0603, Manufacturer=AVX, Supplier Part Number 1=478-3699-1-ND, TempCo=X7R, Tolerance_%=20, Value1="0.276 ohm", Value2=100V, ValueDisplayed=1000pF
C824: "CAP, CERM, 1 µF, 50 V, +/- 10%, X7R, 0603", Cap_Case=0603, Manufacturer="Taiyo Yuden", Supplier Part Number 1=587-3247-1-ND, TempCo=X7R, Tolerance_%=10, Value1=Unknown, Value2=50V, ValueDisplayed=1µF
C825: "CAP, CERM, 0.1 µF, 16 V, +/- 10%, X7R, 0603", Cap_Case=0603, Manufacturer="Taiyo Yuden", Supplier Part Number 1=587-1240-1-ND, TempCo=X7R, Tolerance_%=10, Value1=Unknown, Value2=16V, ValueDisplayed=0.1µF
D800 D802: "Diode, Switching-Bridge, 600 V, 3.5 A, TH", Manufacturer=Shindengen, Supplier Part Number 1=627-D25XB60-7000, Value1=3.5A, Value2=1.05V
D801 D803: "Diode, Ultrafast, 600V, 8A, TH", Manufacturer="ON Semiconductor", Supplier Part Number 1=MUR860GOS-ND, Value1=8A, Value2=600V
D804: "Diode, Zener, 12 V, 500 mW, SOD-123", Manufacturer="ON Semiconductor", Power_W=0.5, Supplier Part Number 1=MMSZ4699T1GOSCT-ND, Value1=0.5W
D805: "Diode, Ultrafast, 100 V, 0.25 A, SOD-323", Manufacturer="NXP Semiconductor", Supplier Part Number 1=568-5003-1-ND, Value1=0.25A, Value2=1.4V
F800: "Fuse, 15 A, 250 VDC, TH", Irating_A=15A, Manufacturer=Littelfuse, Supplier Part Number 1=F4638-ND
GND: "Test Point, Miniature, Black, TH", Color=Black, Manufacturer=Keystone, Supplier Part Number 1=36-5001-ND
H800 H802 H803 H804: library part 513201B02500G, "BOARD LEVEL HEATSINK .5\" TO-220", Manufacturer=Aavid, Supplier Part Number 1=HS403-ND
H801: "HEATSINK VERT MAX CLIP, BLACK, 4.25 INCHES", Manufacturer=Aavid, Supplier Part Number 1=782653B04250G-ND
J800: "AC Receptacle, 10A 250VAC", Manufacturer="Qualtek Electronics Corporation", Supplier Part Number 1=Q220-ND
J801 J802: "Conn Term Block, 2POS, 5.08mm, TH", Manufacturer="Phoenix Contact", Supplier Part Number 1=277-1263-ND
K800: "Relay, SPDT ( 1 Form C), 16A, 12 VDC, TH", Coil Current="30 mA", Coil Power="360 mW", Coil Resistance="400 ohms", Coil Voltage="12 VDC", Contact Rating=16A, Manufacturer="SONG CHUAN", Supplier Part Number 1=893-875B1CCFS12VDC, Turn Off Voltage (Min)="0.6 VDC", Turn On Voltage (Max)="9 VDC"
L800 L803: "Transformer, 160 uH, TH", Manufacturer=TDK
L801 L802: "Coupled inductor, 7 mH, 7 A, 0.02 ohm, TH", Manufacturer="Wurth Elektronik", Supplier Part Number 1=732-5589-ND, ValueDisplayed=7mH
Q800 Q802: library part IPW60R125CP, "MOSFET N-CH 600V 53A TO247", Alternate Manufacturer=None, Manufacturer="Infineon Technologies", Supplier Part Number 1=IPW65R065C7XKSA1, Value1="? ohm"
Q801 Q803: library part "FMMT718TA, Diodes Inc.", "Transistor, PNP, 20V, 1.5A, SOT-23", Manufacturer="Diodes Inc.", Supplier Part Number 1=FMMT718CT-ND, Value1=1.5A, Value2=6
R800 R802 R807: "RES, 432 k, 1%, 0.25 W, 1206", Manufacturer=Vishay-Dale, Power_W=0.25, Supplier Part Number 1=541-432KFCT-ND, TempCo="100 ppm/C", Tolerance_%=1, Value1=1%, Value2=0.25W, Value_Code=432k
R801 R812: "RES, 3.00, 1%, 0.25 W, 1206", Manufacturer="Yageo America", Power_W=0.25, Supplier Part Number 1=311-3.00FRCT-ND, TempCo="200 ppm/C", Tolerance_%=1, Value1=1%, Value2=0.25W, Value_Code=3R00, ValueDisplayed=3.00
R803 R804 R805: "RES, 0.02, 1%, 1 W, 2010", Manufacturer="Stackpole Electronics Inc", Power_W=1, Supplier Part Number 1=CSRN2010FK20L0CT-ND, TempCo="250 ppm/C", Value1=1%, Value2=1W, Value_Code=R020, ValueDisplayed=0.02
R806 R814: "RES, 10.0 k, 1%, 0.125 W, 0805", Manufacturer=Vishay-Dale, Power_W=0.125, Supplier Part Number 1=541-10.0KCCT-ND, TempCo="100 ppm/C", Tolerance_%=1, Value1=1%, Value2=0.125W, Value_Code=10k0, ValueDisplayed=10.0k
R808: "RES, 10, 5%, 10 W, TH", Manufacturer=Ohmite, Power_W=10, TempCo="400 ppm/C", Tolerance_%=5, Value1=5%, Value2=10W, Value_Code=10R0
R810 R811: "RES, 75, 5%, 0.25 W, 1206", Manufacturer=Vishay-Dale, Power_W=0.25, Supplier Part Number 1=541-75ECT-ND, TempCo="200 ppm/C", Tolerance_%=5, Value1=5%, Value2=0.25W, Value_Code=75R0, ValueDisplayed=75
R815 R816: "RES, 20.5 k, 1%, 0.1 W, 0603", Manufacturer=Vishay-Dale, Power_W=0.1, Supplier Part Number 1=541-20.5KHCT-ND, TempCo="100 ppm/C", Tolerance_%=1, Value1=1%, Value2=0.1W, Value_Code=20k5, ValueDisplayed=20.5k
R817: "RES, 3.01 M, 1%, 0.125 W, 0805", Manufacturer=Vishay-Dale, Power_W=0.125, Supplier Part Number 1=541-3.01MCCT-ND, TempCo="100 ppm/C", Tolerance_%=1, Value1=1%, Value2=0.125W, Value_Code=3M01, ValueDisplayed=3.01M
R818 R819 R821 R822 R826: "RES, 2.74 M, 1%, 0.125 W, 0805", Manufacturer=Vishay-Dale, Power_W=0.125, Supplier Part Number 1=541-2.74MCCT-ND, TempCo="100 ppm/C", Tolerance_%=1, Value1=1%, Value2=0.125W, Value_Code=2M74, ValueDisplayed=2.74M
R820 R823 R827: "RES, 2.87 M, 1%, 0.125 W, 0805", Manufacturer=Vishay-Dale, Power_W=0.125, Supplier Part Number 1=541-2.87MCCT-ND, TempCo="100 ppm/C", Tolerance_%=1, Value1=1%, Value2=0.125W, Value_Code=2M87, ValueDisplayed=2.87M
R824 R825 R832 R835: "RES, 133 k, 1%, 0.1 W, 0603", Manufacturer=Vishay-Dale, Power_W=0.1, Supplier Part Number 1=541-133KHCT-ND, TempCo="100 ppm/C", Tolerance_%=1, Value1=1%, Value2=0.1W, Value_Code=133k
R828: "RES, 100, 1%, 0.1 W, 0603", Manufacturer=Vishay-Dale, Power_W=0.1, Supplier Part Number 1=541-100HCT-ND, TempCo="100 ppm/C", Tolerance_%=1, Value1=1%, Value2=0.1W, Value_Code=100R, ValueDisplayed=100
R829: "RES, 15.0 k, 1%, 0.1 W, 0603", Manufacturer=Vishay-Dale, Power_W=0.1, Supplier Part Number 1=541-15.0KHCT-ND, TempCo="100 ppm/C", Tolerance_%=1, Value1=1%, Value2=0.1W, Value_Code=15k0, ValueDisplayed=15.0k
R830: "RES, 11.3 k, 1%, 0.1 W, 0603", Manufacturer=Vishay-Dale, Power_W=0.1, Supplier Part Number 1=541-11.3KHCT-ND, TempCo="100 ppm/C", Tolerance_%=1, Value1=1%, Value2=0.1W, Value_Code=11k3, ValueDisplayed=11.3k
R831: "RES, 82.5 k, 1%, 0.1 W, 0603", Manufacturer=Vishay-Dale, Power_W=0.1, Supplier Part Number 1=541-82.5KHCT-ND, TempCo="100 ppm/C", Tolerance_%=1, Value1=1%, Value2=0.1W, Value_Code=82k5, ValueDisplayed=82.5k
R833: "RES, 121 k, 1%, 0.1 W, 0603", Manufacturer=Vishay-Dale, Power_W=0.1, Supplier Part Number 1=541-121KHCT-ND, TempCo="100 ppm/C", Tolerance_%=1, Value1=1%, Value2=0.1W, Value_Code=121k
R834: "RES, 47.5 k, 1%, 0.1 W, 0603", Manufacturer="Yageo America", Power_W=0.1, Supplier Part Number 1=311-47.5KHRCT-ND, TempCo="200 ppm/C", Tolerance_%=1, Value1=1%, Value2=0.1W, Value_Code=47k5, ValueDisplayed=47.5k
RV800: "Varistor 275V RMS 10MM Radial, TH", Manufacturer="EPCOS Inc", Supplier Part Number 1=495-1433-ND
U801: "Natural Interleaving Transition Mode PFC Controller with Improved Light Load Efficiency, D0016A (SOIC-16)", Alternate Manufacturer="Texas Instruments", Alternate PartNumber=UCC28064D

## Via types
v1: diameter 20, hole 10, Top Layer to Bottom Layer, 54 vias

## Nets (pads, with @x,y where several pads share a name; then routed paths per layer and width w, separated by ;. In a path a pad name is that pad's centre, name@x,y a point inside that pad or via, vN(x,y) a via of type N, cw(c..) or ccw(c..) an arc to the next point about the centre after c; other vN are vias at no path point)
12V1: 12V.1 C812.1 C814.2 C817.1 R810.2 R811.2 U801.12 | length 9720.7
  Top Layer w25: v1(5030,4520) 5060.37,4489.63 5710.37,4489.63 12V.1@5800,4400
  Bottom Layer w25: C814.2@2220,860 R810.2@2137.09,860 R811.2@2137.09,760 2137.09,322.91 2300,160 5750,160 5817.54,227.54 5817.54,755.69 5822.5,760.65 5822.5,1130.03 5817.54,1134.99 5817.54,4382.46 12V.1@5800,4400 ; C817.1@5030,4465 v1(5030,4520) ; C817.1@5035,4460 5035,4440 5080,4395 U801.12@5080,4337.28
  Bottom Layer w50: C812.1@5700,4460 5740,4460 12V.1@5800,4400
GD1: Q801.1 R801.1 U801.14 | length 3108.6
  Bottom Layer w20: Q801.1@3682.76,3142.6 3802.6,3142.6 3820,3160 3820,3460 4168.87,3808.87 4168.87,4548.87 4260,4640 5160,4640 5180,4620 U801.14@5180,4337.28
  Bottom Layer w25: R801.1@3600,3122.91 3619.69,3142.6 Q801.1@3682.76,3142.6
GD2: Q803.1 R812.1 U801.11 | length 4507.5
  Bottom Layer w20: Q803.1@3642.76,1702.6 3792.02,1702.6 3847.87,1758.45 3847.87,2138.45 4021.55,2312.13 4121.55,2312.13 4197.87,2388.45 4197.87,2961.55 3925.75,3233.67 3925.75,3427.49 4253.62,3755.36 4253.62,4514.2 4291.55,4552.13 4967.87,4552.13 4985,4535 4985,4420 5030,4375 U801.11@5030,4337.28
  Bottom Layer w25: R812.1@3550,1682.91 3569.69,1702.6 Q803.1@3642.76,1702.6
